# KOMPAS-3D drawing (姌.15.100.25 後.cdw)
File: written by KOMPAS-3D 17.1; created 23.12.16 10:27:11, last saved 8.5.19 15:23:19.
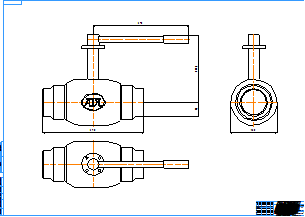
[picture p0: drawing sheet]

Sheet 1: A0, landscape

Title block, sheet 1: name: КШ.15.100.25 сс; material: Внимание! Данный продукт является объектом авторского права ООО «Торговый Дом АДЛ». / Запрещается изменение, копирование, распространение / (в том числе путем копирования на другие сайты и ресурсы в Интернете) / или любое иное использование информации и объектов без предварительного / согласия правообладателя (ООО «Торговый Дом АДЛ»).; sheets: 1; organisation: ООО "Торговый дом АДЛ"; sheet format: A0; stored path: C:\Users\tra\Desktop\2д чертежи\Шаровые краны БИВАЛ\КШ_Бивал_серия_14_15\KOMPAS_2D\КШ.15.100.25 сс.cdw

Views: Вид 1, Проекционный вид 2, Проекционный вид 3
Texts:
  Klimkovich
  ADL
Dimensions and other numbers on the sheet: 390; 370; 258,4; 54; 180; 1:1; 1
